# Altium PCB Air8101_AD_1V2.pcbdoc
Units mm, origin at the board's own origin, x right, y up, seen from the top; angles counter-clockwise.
Board outline 31.95 x 30.7 mm, 2 copper layers (Top Layer, Bottom Layer), stack 1.58 mm thick; 1 components, 0 nets, 79 pads, 0 vias.
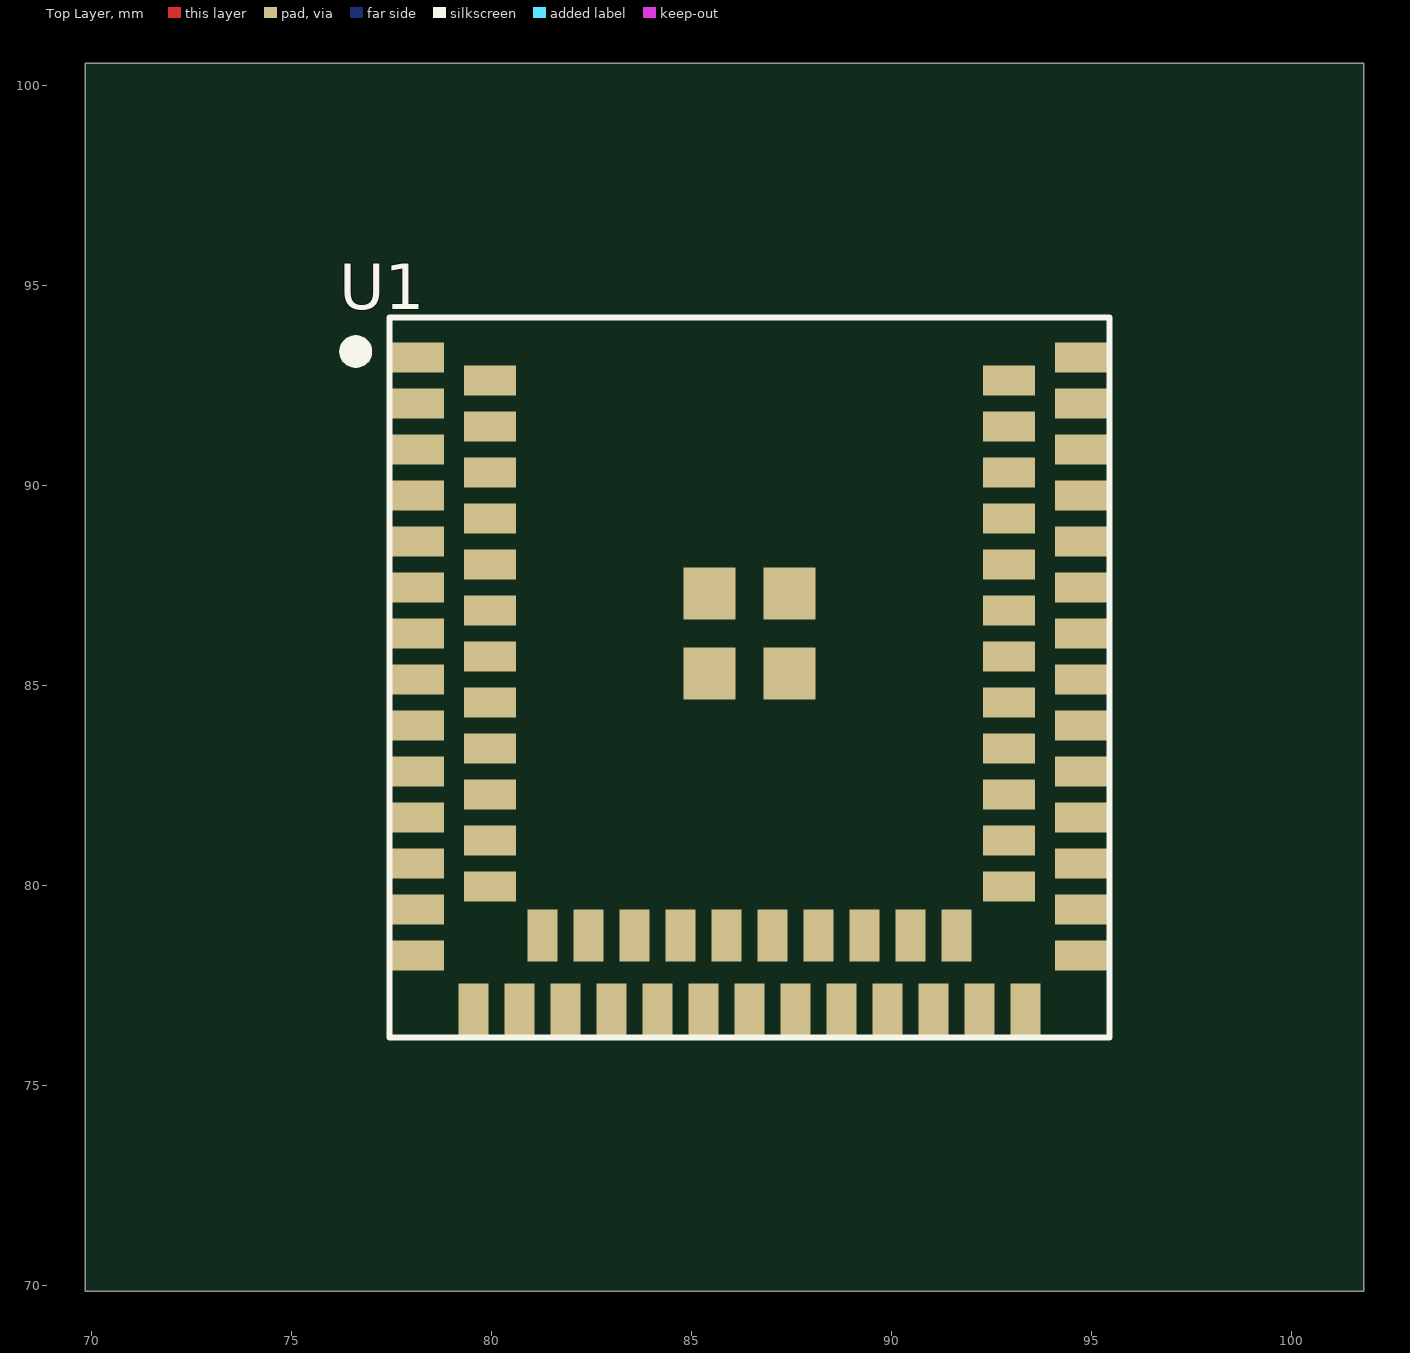
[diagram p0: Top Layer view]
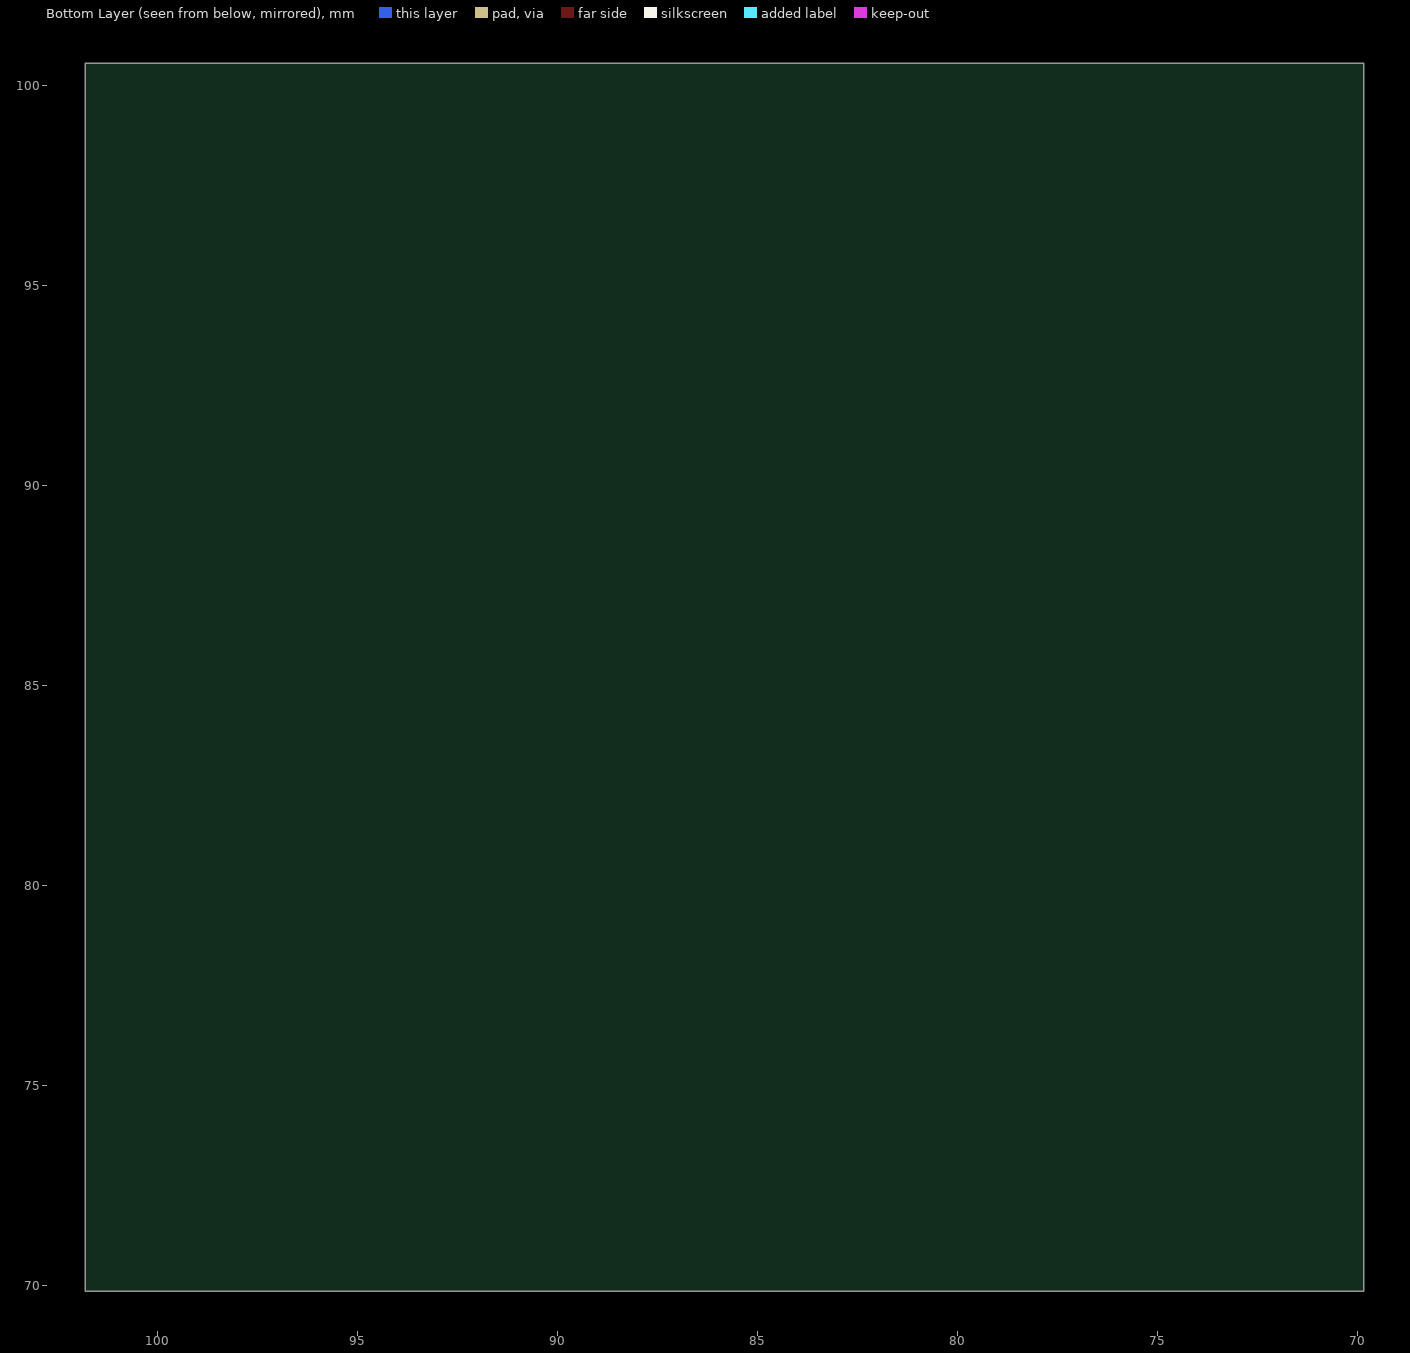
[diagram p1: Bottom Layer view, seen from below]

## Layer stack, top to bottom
Top Solder Mask Layer: solder mask 0.01, Dk 3.3
Top Layer: signal copper 0.035
Dielectric1: surface 1.51, FR4, Dk 4.5
Bottom Layer: signal copper 0.035
Bottom Solder Mask Layer: solder mask 0.01, Dk 3.3

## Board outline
101.801,69.85 69.85,69.85 69.85,100.55 101.801,100.55

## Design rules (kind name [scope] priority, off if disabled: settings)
BoardOutlineClearance copperThickness1oz [All] p0: genericclearance=0.254 ignorepadtopadclearanceinfootprint=FALSE except(0: Arc-SplitContinuation Track-SplitContinuation SMDPad-SplitContinuation THPad-SplitContinuation Via-SplitContinuation Fill-SplitContinuation Poly-SplitContinuation Region-SplitContinuation Text-SplitContinuation)
BoardOutlineClearance copperThickness2oz [All] p0: genericclearance=0.254 ignorepadtopadclearanceinfootprint=FALSE except(0: Arc-SplitContinuation Track-SplitContinuation SMDPad-SplitContinuation THPad-SplitContinuation Via-SplitContinuation Fill-SplitContinuation Poly-SplitContinuation Region-SplitContinuation Text-SplitContinuation)
BoardOutlineClearance otherClearance [All] p0: genericclearance=0.254 ignorepadtopadclearanceinfootprint=FALSE except(0: Arc-SplitContinuation Track-SplitContinuation SMDPad-SplitContinuation THPad-SplitContinuation Via-SplitContinuation Fill-SplitContinuation Poly-SplitContinuation Region-SplitContinuation Text-SplitContinuation)
Clearance copperThickness1oz [All] p1: gap=0.178 ignorepadtopadclearanceinfootprint=FALSE
Clearance copperThickness2oz [All] p1: gap=0.178 ignorepadtopadclearanceinfootprint=FALSE
Clearance otherClearance [All] p1: gap=0.178 ignorepadtopadclearanceinfootprint=FALSE
DiffPairsRouting differentialPair [All] p1: maxuncoupledlength=10 minlimit=6 maxlimit=Infinity mostfreqgap=6 toplayer_minwidth=5 toplayer_prefwidth=10 toplayer_maxwidth=100 bottomlayer_minwidth=5 bottomlayer_prefwidth=10 bottomlayer_maxwidth=100
PasteMaskExpansion pasteMaskExpansion [All] p1: expansion=0
PlaneConnect innerPlane [All] p1: planeconnectstyle=Relief reliefexpansion=0.508 reliefentries=4 reliefconductorwidth=0.254 reliefairgap=0.254
PolygonConnect copperRegion [All] p1: connectstyle=Relief reliefentries=4 reliefconductorwidth=10 polygonreliefangle="90 Angle" airgapwidth=10
RoutingVias viaSize [All] p1: viastyle="Through Hole" holewidth=12.0078 minholewidth=11.811 maxholewidth=248.0314 width=12.0078 minwidth=11.811 maxwidth=248.0314
SolderMaskExpansion solderMaskExpansion [All] p1: useseparateexpansions=TRUE expansion=2 expansionbottom=2
Width copperThickness1oz [All] p1: maxlimit=100 minlimit=5 preferedwidth=10
Width copperThickness2oz [All] p1: maxlimit=100 minlimit=8 preferedwidth=10

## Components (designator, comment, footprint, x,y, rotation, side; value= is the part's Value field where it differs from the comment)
U1 "" AIR8101A-PADS 86.451,86.3 r0 top

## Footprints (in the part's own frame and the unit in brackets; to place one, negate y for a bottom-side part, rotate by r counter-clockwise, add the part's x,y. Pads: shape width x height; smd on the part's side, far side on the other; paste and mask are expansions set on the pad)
AIR8101A-PADS [mm]
  rect 1.3x0.75 smd: 1(-8.29,6.9) 2(-8.29,5.75) 3(-8.29,4.6) 4(-8.29,3.45) 5(-8.29,2.3) 6(-8.29,1.15) 7(-8.29,0) 8(-8.29,-1.15) 9(-8.29,-2.3) 10(-8.29,-3.45) 11(-8.29,-4.6) 12(-8.29,-5.75) 13(-8.29,-6.9) 14(-8.29,-8.05) 28(8.29,-8.05) 29(8.29,-6.9) 30(8.29,-5.75) 31(8.29,-4.6) 32(8.29,-3.45) 33(8.29,-2.3) 34(8.29,-1.15) 35(8.29,0) 36(8.29,1.15) 37(8.29,2.3) 38(8.29,3.45) 39(8.29,4.6) 40(8.29,5.75) 41(8.29,6.9) 42(6.49,6.325) 43(6.49,5.175) 44(6.49,4.025) 45(6.49,2.875) 46(6.49,1.725) 47(6.49,0.575) 48(6.49,-0.575) 49(6.49,-1.725) 50(6.49,-2.875) 51(6.49,-4.025) 52(6.49,-5.175) 53(6.49,-6.325) 64(-6.49,-6.325) 65(-6.49,-5.175) 66(-6.49,-4.025) 67(-6.49,-2.875) 68(-6.49,-1.725) 69(-6.49,-0.575) 70(-6.49,0.575) 71(-6.49,1.725) 72(-6.49,2.875) 73(-6.49,4.025) 74(-6.49,5.175) 75(-6.49,6.325)
  rect 0.75x1.3 smd: 15(-6.9,-9.4) 16(-5.75,-9.4) 17(-4.6,-9.4) 18(-3.45,-9.4) 19(-2.3,-9.4) 20(-1.15,-9.4) 21(0,-9.4) 22(1.15,-9.4) 23(2.3,-9.4) 24(3.45,-9.4) 25(4.6,-9.4) 26(5.75,-9.4) 27(6.9,-9.4) 54(5.175,-7.55) 55(4.025,-7.55) 56(2.875,-7.55) 57(1.725,-7.55) 58(0.575,-7.55) 59(-0.575,-7.55) 60(-1.725,-7.55) 61(-2.875,-7.55) 62(-4.025,-7.55) 63(-5.175,-7.55)
  rect 1.3x1.3 smd: 76(-1,1) 77(1,1) 78(1,-1) 79(-1,-1)
  silkscreen extent -10.25,-10.1 9,7.9

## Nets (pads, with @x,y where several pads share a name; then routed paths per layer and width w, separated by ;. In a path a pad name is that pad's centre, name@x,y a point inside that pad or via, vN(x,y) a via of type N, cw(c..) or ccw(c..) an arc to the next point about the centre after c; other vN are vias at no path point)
pads on no net: U1.1 U1.2 U1.3 U1.4 U1.5 U1.6 U1.7 U1.8 U1.9 U1.10 U1.11 U1.12 U1.13 U1.14 U1.15 U1.16 U1.17 U1.18 U1.19 U1.20 U1.21 U1.22 U1.23 U1.24 U1.25 U1.26 U1.27 U1.28 U1.29 U1.30 U1.31 U1.32 U1.33 U1.34 U1.35 U1.36 U1.37 U1.38 U1.39 U1.40 U1.41 U1.42 U1.43 U1.44 U1.45 U1.46 U1.47 U1.48 U1.49 U1.50 U1.51 U1.52 U1.53 U1.54 U1.55 U1.56 U1.57 U1.58 U1.59 U1.60 U1.61 U1.62 U1.63 U1.64 U1.65 U1.66 U1.67 U1.68 U1.69 U1.70 U1.71 U1.72 U1.73 U1.74 U1.75 U1.76 U1.77 U1.78 U1.79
